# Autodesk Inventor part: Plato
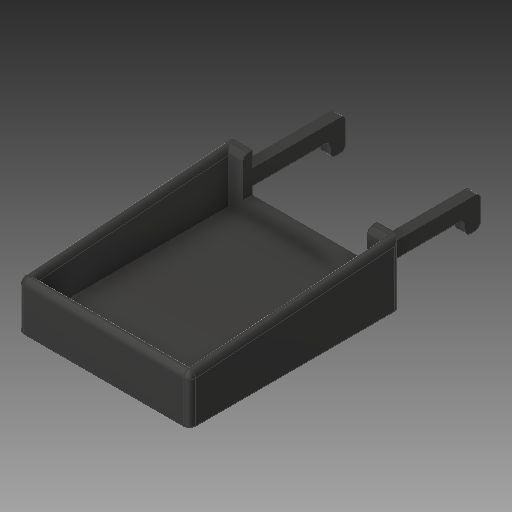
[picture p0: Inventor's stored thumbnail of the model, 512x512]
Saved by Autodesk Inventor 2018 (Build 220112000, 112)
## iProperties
Created: 2022-01
Part Number: Plato
Material: Plástico, negro opaco
Document SubType Name: Modeling
Designer: Asus
Density: 0.952 g/cm^3
Appearance: Suave - Negro
Mass: 1410.66 g
Surface Area: 2335.19 cm^2
Volume: 1481.79 cm^3
Author: Asus
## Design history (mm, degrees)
sketch "Boceto1"
  geometry: L1 (-110, 0.114)-(-110, 270.114); L2 (-110, 0.114)-(110, 0.114); L3 (110, 0.114)-(110, 270.114); L4 (110, 270.114)-(-110, 270.114); L5 (-110, 270.114)-(-110, 0.114); 1 further point
  constraints: 10 end point, 2 parallel, 1 horizontal, 1 perpendicular
  dimensions: "d2" = 110 distance of point (0, 0) L1.start; "d3" = 270 distance of L1.start L1.end; "d4" = 220 distance of L4.end L3.end; "d5" = 270 distance of L3.end L2.end
extrude "Extrusión1" new body sketch "Boceto1" distance "d6" = 80; taper "d7" = 0 deg
sketch "Boceto2"
  geometry: L1 (97.5, -257.5)-(-97.5, -257.5); L2 (-97.5, -257.5)-(-97.5, -12.5); L3 (-97.5, -12.5)-(97.5, -12.5); L4 (97.5, -12.5)-(97.5, -257.5); L5 (97.5, -257.5)-(-97.5, -12.5); L6 (-97.5, -257.5)-(97.5, -12.5); 2 further points
  constraints: 12 end point, 2 midpoint, 2 parallel, 1 horizontal, 1 perpendicular
  dimensions: "d8" = 195 distance of L2.end L3.end; "d9" = 245 distance of L1.end L2.end
extrude "Extrusión2" cut sketch "Boceto2" distance "d10" = 65; taper "d11" = 0 deg
sketch "Boceto3"
  geometry: L1 (0, 80)-(270, 80) reference; L2 (0, 80)-(0, 60); L3 (0, 0)-(0, 80) reference; L4 (270, 0)-(270, 80) reference; L5 (0, 60)-(270, 80); L6 (270, 80)-(0, 80); 1 further point
  constraints: 6 end point, 1 perpendicular, 1 point on line
  dimensions: "d12" = 20 distance of L1.start L2.end
extrude "Extrusión3" cut sketch "Boceto3" distance "d13" = 220; taper "d14" = 0 deg
fillet "Empalme1" dims "d15" = 7.5
sketch "Boceto4"
  geometry: L1 (22.5, 80)-(182.5, 80); L2 (182.5, 80)-(182.5, 30); L3 (182.5, 30)-(22.5, 30); L4 (22.5, 30)-(22.5, 80); L5 (22.5, 80)-(182.5, 30); L6 (182.5, 80)-(22.5, 30); 2 further points
  constraints: 12 end point, 2 midpoint, 2 parallel, 1 horizontal, 1 perpendicular
  dimensions: "d16" = 160 distance of L2.end L3.end; "d17" = 50 distance of L1.end L2.end
extrude "Extrusión4" cut sketch "Boceto4" distance "d18" = 50; taper "d19" = 0 deg
sketch "Boceto5"
  geometry: L1 (22.5, 60)-(10, 60); L2 (10, 60)-(10, 20); L3 (10, 20)-(22.5, 20); L4 (22.5, 20)-(22.5, 60); L5 (182.5, 60)-(195, 60); L6 (195, 60)-(195, 20); L7 (195, 20)-(182.5, 20); L8 (182.5, 20)-(182.5, 60); 3 further points
  constraints: 16 end point, 4 parallel, 2 horizontal, 2 perpendicular
  dimensions: "d20" = 40 distance of L2.end L1.end; "d21" = 40 distance of L5.end L6.end
extrude "Extrusión5" join sketch "Boceto5" distance "d22" = 120; taper "d23" = 0 deg
sketch "Boceto6"
  geometry: L1 (0, 0)-(120, 0) reference; L2 (0, 0)-(0, 20); L3 (0, -20)-(0, 60) reference; L4 (0, 20)-(100, 20); L5 (100, 20)-(100, 0); L6 (100, 0)-(0, 0); 1 further point
  constraints: 8 end point, 2 perpendicular, 1 vertical
  dimensions: "d24" = 20 distance of L1.start L2.end; "d26" = 100 distance of L2.end L4.end; "d27" = 20 distance of L4.end L5.end
extrude "Extrusión6" cut sketch "Boceto6" distance "d28" = 200; taper "d29" = 0 deg
fillet "Empalme2" dims "d30" = 7.5
node "Sólido1"
